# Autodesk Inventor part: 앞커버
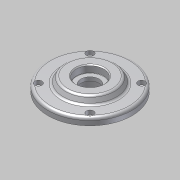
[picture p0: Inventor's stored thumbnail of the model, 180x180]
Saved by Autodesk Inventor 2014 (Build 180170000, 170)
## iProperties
Created: 2013-02
Part Number: 앞커버
Document SubType Name: Modeling
Designer: 한국산업디자인학원[gmhk.co.kr]
Density: 1 g/cm^3
Material: 일반
Appearance: 기본값
Author: 한국산업디자인학원[gmhk.co.kr]
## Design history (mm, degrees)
sketch "스케치1"
  geometry: C1 r 30 at (0, 0) reference; C2 r 46 at (0, 0); A1 r 91.05 centre (0, -48.55) between (34.185, 35.839) and (-34.185, 35.839) reference; A2 r 91.05 centre (48.55, 0) between (-35.839, 34.185) and (-35.839, -34.185) reference; A3 r 3 centre (-33.058, 33.058) between (-34.185, 35.839) and (-35.839, 34.185) reference; A4 r 3 centre (33.058, 33.058) between (35.839, 34.185) and (34.185, 35.839) reference; A5 r 91.05 centre (-48.55, 0) between (35.839, -34.185) and (35.839, 34.185) reference; A6 r 3 centre (33.058, -33.058) between (34.185, -35.839) and (35.839, -34.185) reference; A7 r 91.05 centre (0, 48.55) between (-34.185, -35.839) and (34.185, -35.839) reference; A8 r 3 centre (-33.058, -33.058) between (-35.839, -34.185) and (-34.185, -35.839) reference; 1 further point
  constraints: 1 centre point, 1 coincident
  dimensions: "d37" = 92 diameter of C2
  node "참조1"
  node "참조2"
  node "참조3"
  node "참조4"
  node "참조5"
  node "참조6"
  node "참조7"
  node "참조8"
  node "참조9"
extrude "돌출1" new body sketch "스케치1" distance "d0" = 8; taper "d1" = 0 deg
sketch "스케치2"
  geometry: C1 r 30 at (0, 0); 1 further point
  constraints: 1 centre point, 1 coincident
  dimensions: "d2" = 60 diameter of C1
extrude "돌출2" join sketch "스케치2" distance "d3" = 7; taper "d4" = -30 deg
hole "구멍1" diameter "d7" = 20; stored, may be unused: countersink angle "d11" = 90 deg, drill point angle "d13" = 118 deg; dims "d5" = 10, "d6" = 10, "d8" = 6, "d9" = 30, "d10" = 8, "d12" = 20
sketch "스케치3"
  geometry: C1 r 1.621 at (28.284, 28.284) reference; C2 r 1.621 at (-28.284, 28.284) reference; C3 r 1.621 at (-28.284, -28.284) reference; C4 r 1.621 at (28.284, -28.284) reference; 1 further point
hole "구멍2" sketch "스케치3" at (28.284, 28.284), (28.284, -28.284), (-28.284, -28.284), (-28.284, 28.284) diameter "d14" = 4.5; stored, may be unused: countersink angle "d18" = 90 deg, drill point angle "d20" = 118 deg; dims "d15" = 6, "d16" = 8, "d17" = 4.4, "d19" = 20
extrude "돌출3" join sketch "스케치1" distance "d21" = 12; taper "d22" = 0 deg
hole "구멍3" diameter "d25" = 30; stored, may be unused: countersink angle "d29" = 90 deg, drill point angle "d31" = 0 deg; dims "d23" = 10, "d24" = 10, "d26" = 6, "d27" = 40, "d28" = 12, "d30" = 15
fillet "모깎기1" dims "d32" = 3, "d33" = 0.3
chamfer "모따기1" distance "d34" = 1; stored, may be unused: second distance "d35" = 2, angle "d36" = 45 deg
fillet "모깎기2" dims "d38" = 3
node "솔리드1"
node "참조10"
node "참조11"
node "참조12"
node "참조13"
